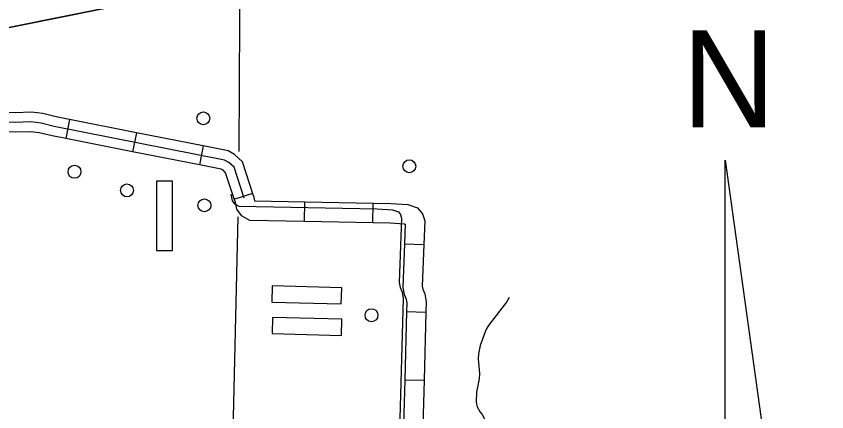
# Model space of a CAD drawing. Extents: x -4786562 to 2097152, y -862751 to 524288.
# Drawn here: x 1377649.7 to 1377823.5, y 379228.6 to 379313.4 of the extents above; entities that cross this region are included whole.
import ezdxf

# ---------------------------------------------------------------- set-up
doc = ezdxf.new("R2010")
doc.units = 0
for name, color, linetype in [('Level 15', 7, 'Continuous'), ('Level 32', 7, 'Continuous'), ('Level 35', 7, 'Continuous'), ('Level 5', 7, 'Continuous'), ('Level 56', 7, 'Continuous'), ('Level 57', 7, 'Continuous'), ('R_Draft', 7, 'Continuous')]:
    doc.layers.add(name, color=color, linetype=linetype)

# ---------------------------------------------------------------- blocks, each defined once
blk = doc.blocks.new('NORTH ARROW VICINITY MAP')
at = {"layer": 'R_Draft'}
for p, q in [((0, 72.55351300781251), (4.85069765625, 37.4946626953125)), ((0, 30.511855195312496), (0, 72.55351300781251))]:
    blk.add_line(p, q, dxfattribs=at)
blk.add_text('N', height=7.8248638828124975, dxfattribs=at).set_placement((-3.4887364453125, 75.19927042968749))

msp = doc.modelspace()

# ---------------------------------------------------------------- linework, layer by layer
at = {"layer": 'Level 32'}
for p, q in [((1377661.1410782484, 379291.28271848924), (1377660.3347742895, 379287.2066564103)), ((1377675.488873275, 379288.4445329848), (1377674.6825693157, 379284.3684432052)), ((1377689.8366960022, 379285.6063197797), (1377689.0303643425, 379281.5302577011)), ((1377696.475739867, 379274.165435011), (1377700.4282303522, 379275.4469674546)), ((1377711.5147989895, 379269.4590220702), (1377711.5960166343, 379273.61331014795)), ((1377726.137825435, 379269.17315368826), (1377726.2190430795, 379273.3274140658)), ((1377732.9456756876, 379264.6116970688), (1377737.0980247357, 379264.461505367)), ((1377733.4084943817, 379250.0912175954), (1377737.5619514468, 379249.9759561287)), ((1377733.0027939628, 379235.4710165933), (1377737.1562510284, 379235.35575512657))]:
    msp.add_line(p, q, dxfattribs=at)
for points in [[(1377698.5888667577, 379274.3839913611), (1377696.4273195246, 379281.0505694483), (1377695.2861728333, 379282.0666487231), (1377694.397266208, 379282.5863917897), (1377657.8763893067, 379289.8107456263), (1377655.049311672, 379290.48342273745), (1377652.9167113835, 379290.7457180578), (1377649.535015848, 379290.6415644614), (1377620.6142213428, 379291.77290520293)], [(1377661.1410782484, 379291.28271848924), (1377658.3185711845, 379291.8410759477), (1377655.4176996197, 379292.53128742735), (1377653.012083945, 379292.8271833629), (1377649.5436583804, 379292.7203428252), (1377646.3478603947, 379292.84538254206)], [(1377675.488873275, 379288.4445329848), (1377661.1410782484, 379291.28271848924)], [(1377660.3347742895, 379287.2066564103), (1377657.4342074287, 379287.7804153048), (1377654.680923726, 379288.43555804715), (1377652.8213388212, 379288.6642527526), (1377649.5263733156, 379288.56278609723), (1377646.1854251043, 379288.69347670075)], [(1377689.8366683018, 379285.6063197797), (1377675.488873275, 379288.4445329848)], [(1377674.6825693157, 379284.36847090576), (1377660.3347742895, 379287.2066564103)], [(1377700.6003330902, 379274.9161719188), (1377698.229758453, 379282.2274219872), (1377696.5133016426, 379283.7557375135), (1377695.14376495, 379284.5565013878), (1377689.8366683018, 379285.6063197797)], [(1377689.0303643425, 379281.5302577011), (1377674.6825693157, 379284.36847090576)], [(1377696.5774004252, 379273.8518385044), (1377694.6248805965, 379279.873716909), (1377694.0590440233, 379280.3775599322), (1377693.6507674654, 379280.61628219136), (1377689.0303643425, 379281.5302577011)], [(1377695.7287979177, 379275.2946428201), (1377696.0314804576, 379273.82898565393), (1377696.5161547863, 379273.1744800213), (1377697.4126513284, 379272.66739604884), (1377727.0876452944, 379272.08723835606), (1377730.4119455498, 379271.90948473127), (1377731.63912976, 379271.4648929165), (1377732.0937214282, 379270.9205795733), (1377732.3318896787, 379270.1499537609), (1377731.8313984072, 379256.31411798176), (1377732.0485697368, 379255.2382611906), (1377732.429866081, 379254.2490790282), (1377732.680111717, 379252.92461092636), (1377730.9607740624, 379190.9657139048), (1377730.7458464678, 379188.13511831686), (1377730.5144648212, 379187.3266814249), (1377729.134318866, 379184.63721950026), (1377728.453165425, 379184.15157565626), (1377727.3847877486, 379183.65756628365), (1377725.5925425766, 379183.3696203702), (1377716.397829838, 379182.4790240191), (1377715.1100370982, 379181.89720430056), (1377714.021881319, 379181.04259080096), (1377710.848991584, 379176.81846995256)], [(1377700.6003330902, 379274.9161719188), (1377700.824318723, 379273.83158949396), (1377700.8384182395, 379273.8236117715), (1377711.5960166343, 379273.61331014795)], [(1377696.5774004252, 379273.8518385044), (1377696.9495279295, 379272.0498427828), (1377697.9692636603, 379270.6727992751), (1377699.7070220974, 379269.6898774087), (1377711.5147989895, 379269.4590220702)], [(1377711.5960166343, 379273.61331014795), (1377726.2190430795, 379273.3274140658)], [(1377726.2190430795, 379273.3274140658), (1377730.023502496, 379273.25303842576), (1377733.6902908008, 379273.0569748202), (1377735.734222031, 379272.3164870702), (1377736.8155912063, 379271.0216861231), (1377737.2808752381, 379269.51622344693), (1377737.0980247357, 379264.461505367)], [(1377711.5147989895, 379269.4590220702), (1377726.137825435, 379269.1731259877)], [(1377726.137825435, 379269.1731259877), (1377729.871925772, 379269.1001353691), (1377732.8537379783, 379268.94069172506), (1377733.0990529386, 379268.85182876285), (1377732.9456756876, 379264.6116970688)], [(1377732.9456756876, 379264.6116970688), (1377732.606428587, 379255.2331366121), (1377732.906950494, 379253.74432189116), (1377733.2835654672, 379252.7673002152), (1377733.4572471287, 379251.8480339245), (1377733.4084943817, 379250.09124529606)], [(1377737.0980247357, 379264.461505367), (1377736.7765059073, 379255.57379643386), (1377736.9103266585, 379254.9108975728), (1377737.296304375, 379253.90955492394), (1377737.6231139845, 379252.17988501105), (1377737.5619514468, 379249.9759561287)], [(1377733.4084943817, 379250.0912175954), (1377733.0027939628, 379235.4710165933)], [(1377737.5619514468, 379249.97598382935), (1377737.1562510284, 379235.3557828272)], [(1377733.0027939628, 379235.4710165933), (1377732.5970935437, 379220.85081559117)], [(1377737.1562510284, 379235.3557828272), (1377736.7505506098, 379220.7355818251)]]:
    msp.add_lwpolyline(points, dxfattribs=at)
at = {"layer": 'Level 35'}
msp.add_lwpolyline([(1377755.4088132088, 379253.12238700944), (1377754.815659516, 379252.0918530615), (1377751.1279296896, 379247.3273800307), (1377750.4797951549, 379246.3204695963), (1377749.2077362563, 379242.7836516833), (1377748.8200411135, 379241.0605467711), (1377748.7546404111, 379239.95169877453), (1377748.9984872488, 379236.7979500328), (1377748.9607592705, 379235.68951754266), (1377748.3978866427, 379232.8005017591), (1377748.3215442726, 379230.6389822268), (1377748.530599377, 379229.6727914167), (1377749.1577369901, 379228.5190410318), (1377749.6083120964, 379228.0273307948), (1377750.0641779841, 379227.2033539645), (1377750.2701583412, 379226.43098302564), (1377750.2240648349, 379225.8486369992), (1377749.3620830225, 379224.3676337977), (1377748.7122033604, 379223.4714419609), (1377747.8072027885, 379221.21427286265)], dxfattribs=at)
at = {"layer": 'Level 5'}
for points in [[(1377698.8207747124, 379431.6588306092), (1377697.6287700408, 379326.9347992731), (1377697.4658915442, 379284.4397163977)], [(1377697.260437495, 379270.38947933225), (1377695.1889443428, 379181.4627508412)]]:
    msp.add_lwpolyline(points, dxfattribs=at)
at = {"layer": 'Level 56'}
for centre, radius in [((1377689.847055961, 379291.5340167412), 1.3850215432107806), ((1377662.2250512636, 379280.0665672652), 1.3850209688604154), ((1377733.984192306, 379281.25275484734), 1.3850226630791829), ((1377673.4773238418, 379276.07288624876), 1.3850209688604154), ((1377690.0714017, 379272.8640690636), 1.3850183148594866), ((1377725.8774691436, 379249.3097886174), 1.3850276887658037)]:
    msp.add_circle(centre, radius, dxfattribs=at)
at = {"layer": 'Level 57'}
for p, q in [((1377679.7685334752, 379278.0672060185), (1377679.7685334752, 379263.17820009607)), ((1377683.23111425, 379278.0672060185), (1377679.7685334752, 379278.0672060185)), ((1377683.23111425, 379263.17820009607), (1377683.23111425, 379278.0672060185)), ((1377679.7685334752, 379263.17820009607), (1377683.23111425, 379263.17820009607)), ((1377704.6158697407, 379255.5957074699), (1377704.519693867, 379252.1344563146)), ((1377719.4991416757, 379255.1820570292), (1377704.6158697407, 379255.5957074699)), ((1377719.402938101, 379251.72080587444), (1377719.4991416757, 379255.1820570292)), ((1377704.519693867, 379252.1344563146), (1377719.402938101, 379251.72080587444)), ((1377704.6609383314, 379248.84926905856), (1377704.5647624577, 379245.3880179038)), ((1377719.5442102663, 379248.43561861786), (1377704.6609383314, 379248.84926905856)), ((1377719.4480066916, 379244.9743951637), (1377719.5442102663, 379248.43561861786)), ((1377704.5647624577, 379245.3880179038), (1377719.4480066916, 379244.9743951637))]:
    msp.add_line(p, q, dxfattribs=at)
at = {"layer": 'R_Draft'}
msp.add_spline([(1378537.1312526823, 379490.139278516), (1378537.1310216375, 379490.1335409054), (1378537.1305980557, 379490.13469612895), (1378537.1308676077, 379490.1295746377), (1378537.1308676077, 379490.1295746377), (1378537.130713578, 379490.1301522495), (1378537.1312141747, 379490.12449165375)], degree=3, dxfattribs=at)

# ---------------------------------------------------------------- block references
at = {"layer": 'Level 15', "xscale": 2.657341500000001, "yscale": 2.657341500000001}
msp.add_blockref('NORTH ARROW VICINITY MAP', (1377801.6988903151, 379089.771478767), dxfattribs=at)

doc.saveas('drawing.dxf')
